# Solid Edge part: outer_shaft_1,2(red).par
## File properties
Author: vinurabandara
Template: iso metric part.par
Last saved by: Nimesh.N
Revision: 6
Application: Solid Edge
Density: 7833.000 kg/m^3
Accuracy: 0.990
Username: Nimesh.N
Material: Steel
Face Style: Steel
Fill Style: ANSI32(Steel)
Virtual Style: Machined steel
Grouping: Metals\Steel
LibraryName: Materials
Coef. of Thermal Exp: 1.3e-05
Thermal Conductivity: 32.0
Specific Heat: 481.0
Modulus of Elasticity: 199947953000.0
Poisson's Ratio: 0.29
Yield Stress: 262000766.0
Ultimate Stress: 358527364.0
Elongation: 0.0
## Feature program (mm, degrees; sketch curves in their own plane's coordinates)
sketch for "unnamed Protrusion 1" #1 plane through (0, 0, 0) normal (0, -1, 0) x-axis (1, 0, 0)
  circle centre (0, 0) radius 12.5
sketch for "unnamed Protrusion 1" #2 plane through (0, 0, 0) normal (0, -1, 0) x-axis (1, 0, 0)
  circle centre (0, 0) radius 7.5
extrude "unnamed Protrusion 1" add finite 222.5 along +normal
sketch for "ExtrudedProtrusion_2" #1 plane through (0, -222.5, 0) normal (0, -1, 0) x-axis (1, 0, 0)
  circle centre (0, 0) radius 7.5
sketch for "ExtrudedProtrusion_2" #2 plane through (0, -222.5, 0) normal (0, -1, 0) x-axis (1, 0, 0)
  circle centre (0, 0) radius 17.5
extrude "ExtrudedProtrusion_2" add finite 40 along +normal
sketch for "ExtrudedProtrusion_3" #1 plane through (0, 0, 0) normal (0, 1, 0) x-axis (0, 0, -1)
  circle centre (0, 0) radius 7.5
sketch for "ExtrudedProtrusion_3" #2 plane through (0, 0, 0) normal (0, 1, 0) x-axis (0, 0, -1)
  circle centre (0, 0) radius 17.5
extrude "ExtrudedProtrusion_3" add finite 30 along +normal
sketch for "ExtrudedCutout_4" plane through (0, 0, 7.6) normal (0, 0, 1) x-axis (1, 0, 0)
extrude "ExtrudedCutout_4" cut through along +normal  Profile_Plane1_Distance = 7.6 mm
sketch for "ExtrudedCutout_5" plane through (1.6449, 0, -7.4198) normal (-0.21644, 0, 0.976296) x-axis (0.976296, 0, 0.21644)
extrude "ExtrudedCutout_5" cut through along -normal  Profile_Plane1_Distance = 7.6 mm
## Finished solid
Body 1: solid body, 15 faces, 22 edges, 8 vertices.
  Faces by surface: plane 10, cylinder 5
  Edges by curve: circle 11, line 10, intersection 1
Bounding box of the edges (mm): 35.000 x 292.500 x 35.000, from (-17.5, -262.5, -17.5) to (17.5, 30, 17.5).
Cylindrical faces by radius (mm): R6 x1, R7.5 x1, R12.5 x1, R17.5 x2
Planar faces by outward normal: +y 3, +z 1, -y 3, oblique 3
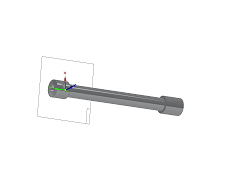
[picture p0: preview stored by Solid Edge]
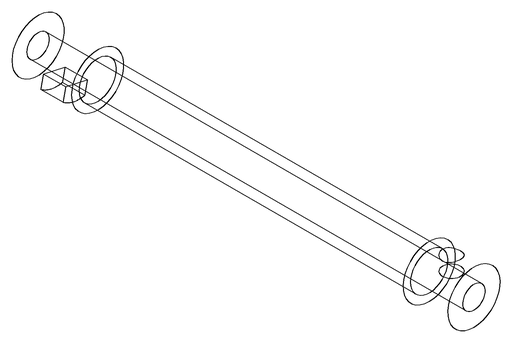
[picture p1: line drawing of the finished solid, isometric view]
